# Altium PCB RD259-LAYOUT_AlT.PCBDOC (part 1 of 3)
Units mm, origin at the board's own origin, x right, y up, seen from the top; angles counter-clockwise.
Board outline 82.5 x 69.38 mm, 2 copper layers (TOP, BOTTOM), stack 0 mm thick; 80 components, 51 nets, 446 pads, 0 vias.
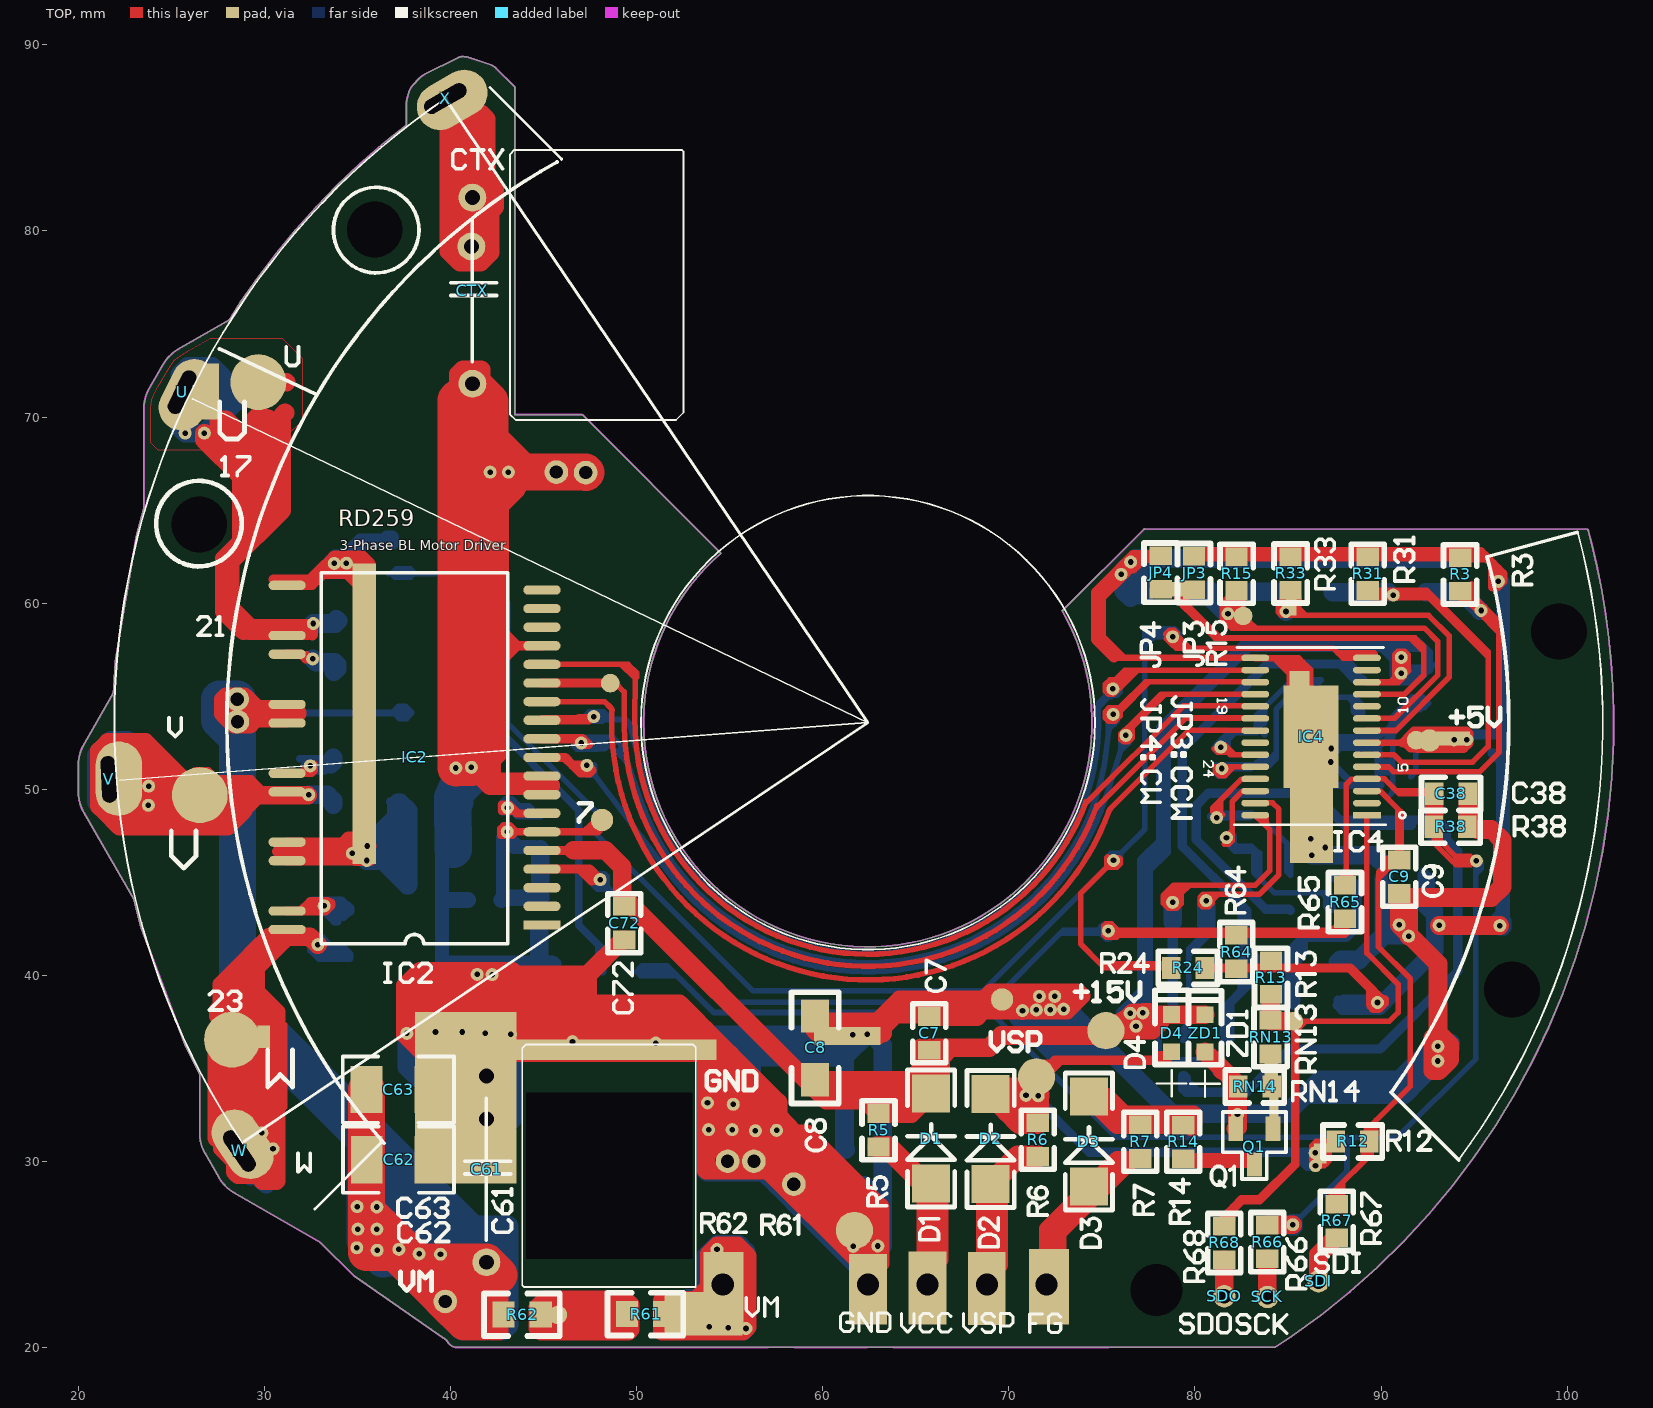
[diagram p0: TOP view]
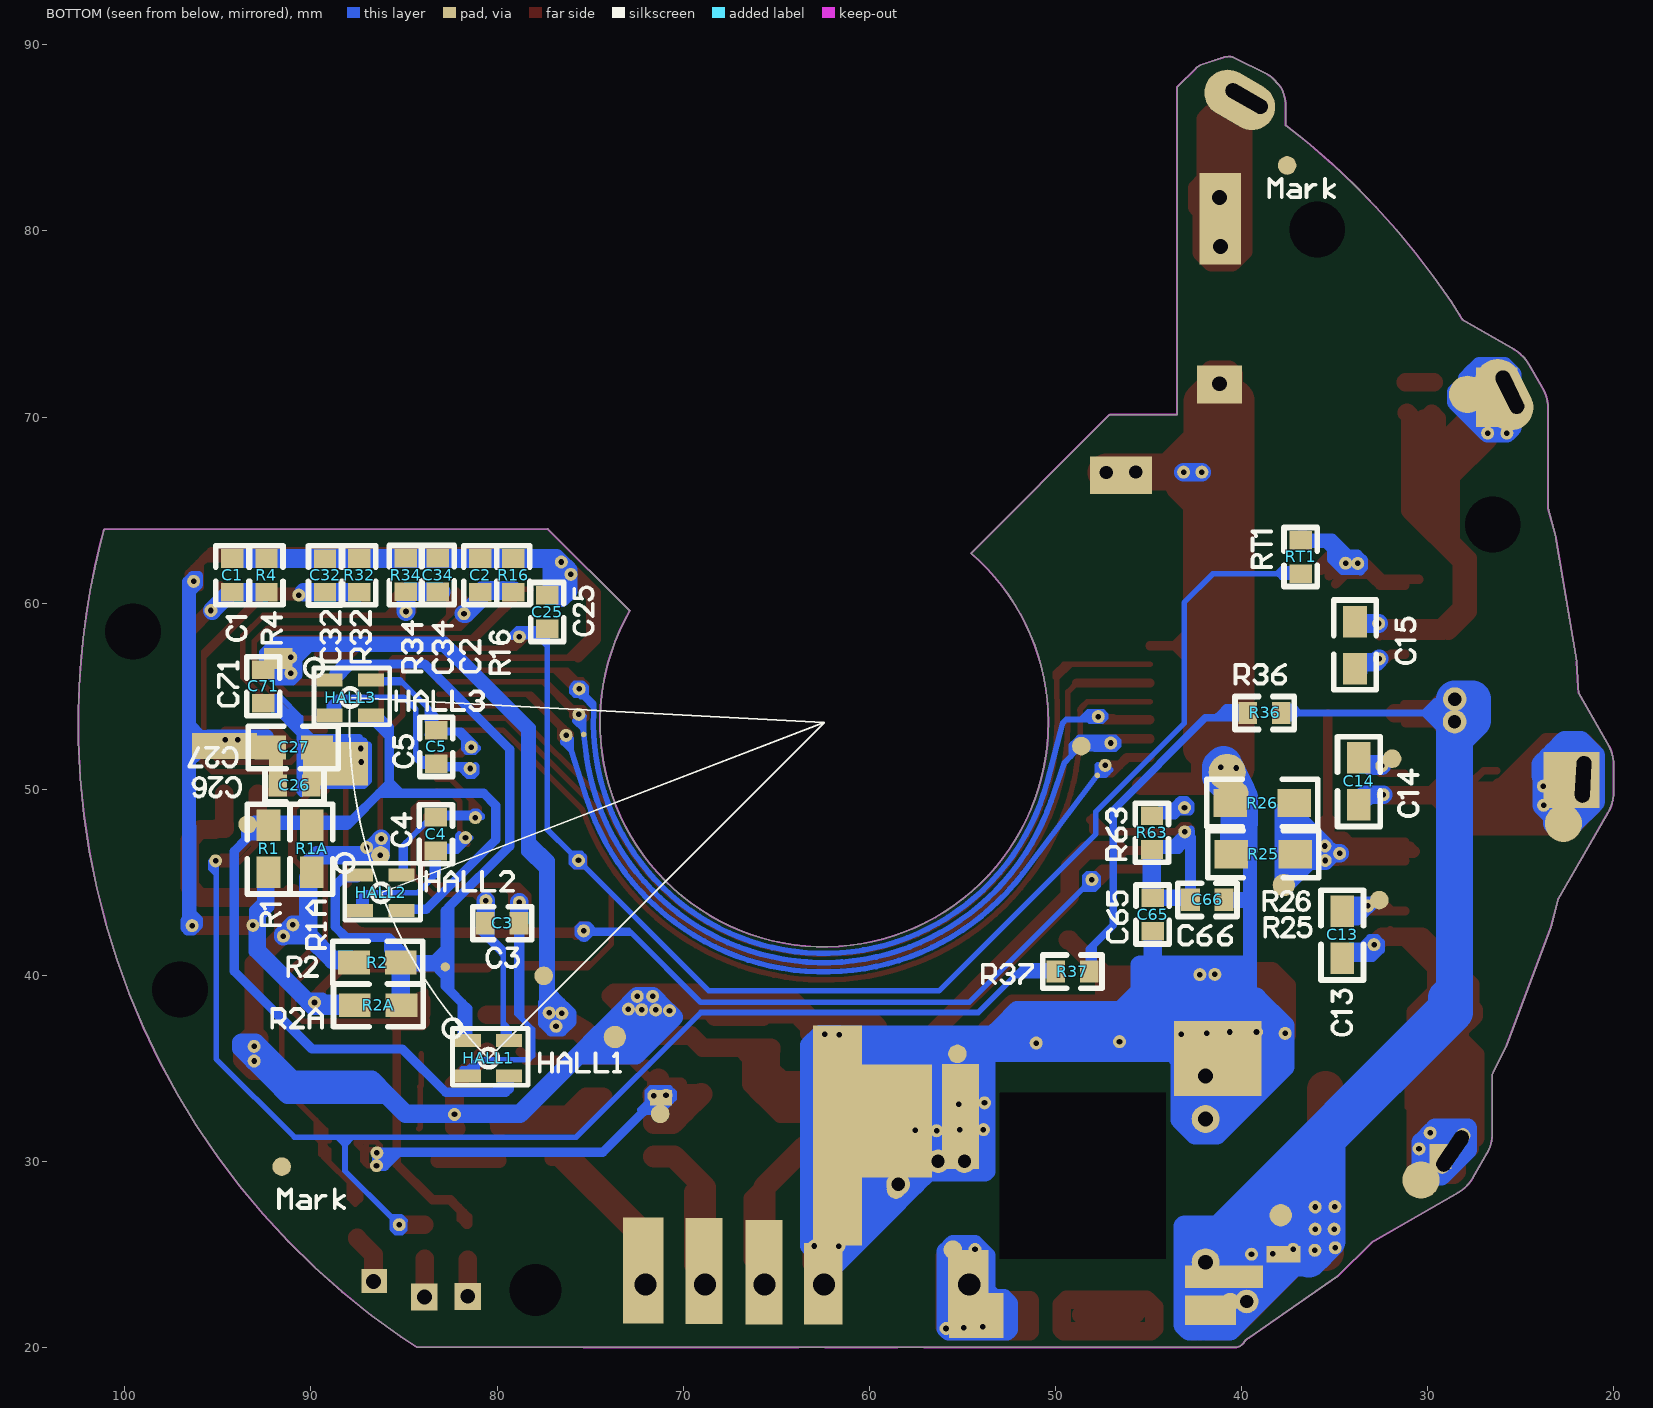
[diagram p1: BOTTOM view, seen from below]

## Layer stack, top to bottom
Top Solder: solder mask 0.0102, Solder Resist, Dk 3.5
TOP: signal copper (thickness not stored)
BOTTOM: signal copper (thickness not stored)
Bottom Solder: solder mask 0.0102, Solder Resist, Dk 3.5

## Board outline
40.344,20 40.34,20 40.337,20.001 40.333,20.001 40.331,20.002 40.259,20.003 40.121,20.042 39.996,20.113 39.893,20.213 39.854,20.277 39.851,20.282 39.849,20.288 39.847,20.293 39.846,20.296 39.823,20.329 39.77,20.39 39.709,20.443 39.642,20.489 39.607,20.508 39.603,20.509 39.595,20.511 39.588,20.514 39.581,20.518 34.873,23.794 34.871,23.795 34.868,23.797 34.865,23.799 34.862,23.802 34.86,23.803 34.847,23.812 34.841,23.818 34.835,23.824 34.83,23.831 34.828,23.834 33.004,25.636 28.356,28.32 28.233,28.391 28.008,28.564 27.807,28.764 27.634,28.989 27.562,29.111 27.561,29.113 27.56,29.116 26.808,30.417 26.807,30.419 26.806,30.422 26.805,30.425 26.804,30.426 26.734,30.549 26.627,30.81 26.555,31.083 26.518,31.362 26.518,31.504 26.518,31.506 26.518,34.672 26.466,34.783 25.765,36.193 25.762,36.196 25.757,36.202 25.753,36.209 25.749,36.216 23.385,42.538 23.384,42.54 23.381,42.546 23.379,42.551 23.377,42.556 23.374,42.568 23.361,42.604 23.359,42.61 23.358,42.617 23.357,42.624 23.357,42.627 22.974,44.093 20.292,48.739 20.221,48.862 20.112,49.125 20.038,49.401 20,49.683 20,49.827 20,49.83 20,49.832 20.001,49.835 20.001,49.836 20.001,51.469 20.038,51.752 20.112,52.027 20.221,52.291 21.877,55.159 21.9,55.476 21.984,56.839 21.983,56.843 21.981,56.853 21.98,56.862 21.98,56.871 23.099,63.5 23.098,63.505 23.096,63.516 23.095,63.527 23.097,63.538 23.102,63.559 23.102,63.562 23.102,63.569 23.102,63.576 23.104,63.583 23.518,65.088 23.518,70.454 23.518,70.596 23.556,70.879 23.629,71.155 23.739,71.418 24.56,72.841 24.63,72.963 24.802,73.186 25,73.386 25.223,73.559 25.345,73.63 25.346,73.631 25.349,73.633 25.351,73.635 25.354,73.637 28.114,75.229 28.139,75.267 28.14,75.269 28.142,75.275 28.144,75.281 28.147,75.286 28.275,75.479 28.275,75.483 28.277,75.493 28.28,75.502 28.284,75.51 28.726,76.198 29.66,77.53 30.646,78.824 31.683,80.077 32.77,81.287 33.904,82.453 35.084,83.572 36.308,84.644 36.83,85.065 37.621,85.677 37.621,86.837 cw(c38.621,86.837) 37.659,87.112 37.754,87.444 cw(c38.716,87.169) 37.987,87.854 38.319,88.207 cw(c39.047,87.522) 38.6,88.417 40.387,89.31 cw(c40.671,88.742) 40.671,89.377 cw(c40.671,88.453) 40.963,89.33 42.158,88.931 cw(c41.947,88.299) 42.437,88.752 43.44,87.748 43.444,87.745 43.45,87.736 43.453,87.727 43.455,87.717 43.455,84.083 43.456,84.081 43.456,84.079 43.456,84.077 43.456,70.128 47.068,70.128 47.078,70.126 47.088,70.122 47.096,70.116 47.099,70.113 54.528,62.683 54.529,62.683 ccw(c62.421,53.577) 72.865,59.587 72.866,59.587 77.265,63.977 77.273,63.983 77.282,63.986 77.292,63.988 101.089,63.963 101.104,63.959 101.117,63.95 101.126,63.938 101.129,63.93 101.131,63.927 101.136,63.92 101.139,63.913 101.142,63.906 101.311,63.271 101.606,62 101.86,60.719 102.072,59.431 102.241,58.137 102.369,56.837 102.454,55.535 102.496,54.23 102.496,52.583 102.397,50.597 102.2,48.618 101.906,46.651 101.513,44.701 101.025,42.774 100.442,40.872 99.765,39.002 98.996,37.168 98.137,35.375 97.191,33.626 96.159,31.926 95.043,30.279 93.848,28.69 92.575,27.162 91.228,25.699 89.81,24.305 88.324,22.983 86.775,21.736 85.166,20.567 84.329,20.02 84.318,20.015 84.307,20.012 84.295,20.011 84.289,20.011 75.37,20.011 75.365,20.009 75.356,20.005 75.347,20.002 75.337,20.001 63.816,20.001 63.806,20.003 63.797,20.005 63.788,20.009 63.783,20.011 62.396,20.011 62.391,20.009 62.382,20.005 62.373,20.002 62.363,20.001 58.508,20.001 58.498,20.002 58.488,20.005 58.479,20.009 58.475,20.011 57.07,20.011 57.065,20.009 57.056,20.005 57.047,20.002 57.037,20.001

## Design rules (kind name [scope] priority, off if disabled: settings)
AssemblyTestPointUsage [All] p0: scope1count=1 scope1_0_kind=Board scope1_0_value=Board scope2count=1 scope2_0_kind=Board scope2_0_value=Board commentlength=0
AssemblyTestpoint [All] p0: scope1count=1 scope1_0_kind=Board scope1_0_value=Board scope2count=1 scope2_0_kind=Board scope2_0_value=Board commentlength=0
Clearance [All] p0: scope1count=1 scope1_0_kind=Board scope1_0_value=Board scope2count=1 scope2_0_kind=Board scope2_0_value=Board commentlength=0 gap=0.15
Clearance [All] p1: gap=0.15 ignorepadtopadclearanceinfootprint=TRUE except(0.2: SMDPad-Fill SMDPad-Poly SMDPad-Region THPad-Fill THPad-Poly THPad-Region; 0.3: Arc-Hole Track-Hole SMDPad-Hole THPad-Hole Via-Hole Fill-Hole Poly-Hole Region-Hole Text-Hole)
ComponentClearance [All] p0: scope1count=1 scope1_0_kind=Board scope1_0_value=Board scope2count=1 scope2_0_kind=Board scope2_0_value=Board commentlength=0 gap=0.254 collisioncheckmode=3
DiffPairsRouting [All] p0: scope1count=1 scope1_0_kind=Board scope1_0_value=Board scope2count=1 scope2_0_kind=Board scope2_0_value=Board commentlength=0
FabricationTestPointUsage [All] p0: scope1count=1 scope1_0_kind=Board scope1_0_value=Board scope2count=1 scope2_0_kind=Board scope2_0_value=Board commentlength=0 valid=0 allowmultiple=FALSE
FabricationTestpoint [All] p0: scope1count=1 scope1_0_kind=Board scope1_0_value=Board scope2count=1 scope2_0_kind=Board scope2_0_value=Board commentlength=0 side=3 testpointundercomponent=TRUE minsize=1.016 maxsize=2.54 preferedsize=1.524 minholesize=0 maxholesize=1.016 preferedholesize=0.813 testpointgrid=0.025
FanoutControl Fanout_BGA [All] p0 off: scope1count=1 scope1_0_kind=Board scope1_0_value=Board scope2count=1 scope2_0_kind=Board scope2_0_value=Board commentlength=69 // Protel DXP Scope 1 Expression Was: IsBGA   Fanout_BGA (Default Rule)
FanoutControl Fanout_LCC [All] p0 off: scope1count=1 scope1_0_kind=Board scope1_0_value=Board scope2count=1 scope2_0_kind=Board scope2_0_value=Board commentlength=69 // Protel DXP Scope 1 Expression Was: IsLCC   Fanout_LCC (Default Rule)
FanoutControl Fanout_SOIC [All] p0 off: scope1count=1 scope1_0_kind=Board scope1_0_value=Board scope2count=1 scope2_0_kind=Board scope2_0_value=Board commentlength=71 // Protel DXP Scope 1 Expression Was: IsSOIC   Fanout_SOIC (Default Rule)
FanoutControl Fanout_Small [All] p0 off: scope1count=1 scope1_0_kind=Board scope1_0_value=Board scope2count=1 scope2_0_kind=Board scope2_0_value=Board commentlength=84 // Protel DXP Scope 1 Expression Was: (CompPinCount < 5)   Fanout_Small (Default Rule)
FanoutControl Fanout_Default [All] p0: scope1count=1 scope1_0_kind=Board scope1_0_value=Board scope2count=1 scope2_0_kind=Board scope2_0_value=Board commentlength=30 // Fanout_Default (Default Rule)
Height [All] p0: scope1count=1 scope1_0_kind=Board scope1_0_value=Board scope2count=1 scope2_0_kind=Board scope2_0_value=Board commentlength=0
HoleSize [All] p0: scope1count=1 scope1_0_kind=Board scope1_0_value=Board scope2count=1 scope2_0_kind=Board scope2_0_value=Board commentlength=0 absolutevalues=TRUE maxlimit=100 minlimit=0.001 maxpercent=80.000 minpercent=20.000
HoleSize [All] p1: absolutevalues=TRUE maxlimit=100 minlimit=0.001 maxpercent=80.000 minpercent=20.000
HoleToHoleClearance [All] p0: scope1count=1 scope1_0_kind=Board scope1_0_value=Board scope2count=1 scope2_0_kind=Board scope2_0_value=Board commentlength=0
HoleToHoleClearance [All] p1: gap=0.4 allowstackedmicrovias=FALSE
LayerPairs [All] p0: scope1count=1 scope1_0_kind=Board scope1_0_value=Board scope2count=1 scope2_0_kind=Board scope2_0_value=Board commentlength=0 enforce=TRUE
MinimumSolderMaskSliver [All] p0: scope1count=1 scope1_0_kind=Board scope1_0_value=Board scope2count=1 scope2_0_kind=Board scope2_0_value=Board commentlength=0
MinimumSolderMaskSliver [All] p1: minsoldermaskwidth=0.1
NetAntennae [All] p0: scope1count=1 scope1_0_kind=Board scope1_0_value=Board scope2count=1 scope2_0_kind=Board scope2_0_value=Board commentlength=0
NetAntennae [All] p1: netantennaetolerance=100
PasteMaskExpansion [All] p0: scope1count=1 scope1_0_kind=Board scope1_0_value=Board scope2count=1 scope2_0_kind=Board scope2_0_value=Board commentlength=0 expansion=0
PlaneClearance [All] p0: scope1count=1 scope1_0_kind=Board scope1_0_value=Board scope2count=1 scope2_0_kind=Board scope2_0_value=Board commentlength=0 clearance=0.001
PlaneClearance [All] p1: clearance=0.001
PlaneConnect [All] p0: scope1count=1 scope1_0_kind=Board scope1_0_value=Board scope2count=1 scope2_0_kind=Board scope2_0_value=Board commentlength=0 planeconnectstyle=Direct reliefexpansion=0.508 reliefentries=4 reliefconductorwidth=0.254 reliefairgap=0.254
PlaneConnect [All] p1: planeconnectstyle=Direct reliefexpansion=0.508 reliefentries=4 reliefconductorwidth=0.254 reliefairgap=0.254
PolygonConnect [All] p0: scope1count=1 scope1_0_kind=Board scope1_0_value=Board scope2count=1 scope2_0_kind=Board scope2_0_value=Board commentlength=0 connectstyle=Direct reliefconductorwidth=0.254 reliefentries=4 polygonreliefangle="90 Angle"
PolygonConnect [All] p1: connectstyle=Direct reliefconductorwidth=0.254 reliefentries=4 polygonreliefangle="90 Angle" airgapwidth=0.254
RoutingCorners [All] p0: scope1count=1 scope1_0_kind=Board scope1_0_value=Board scope2count=1 scope2_0_kind=Board scope2_0_value=Board commentlength=0 cornerstyle=45-Degree minsetback=2.54 maxsetback=2.54
RoutingLayers [All] p0: scope1count=1 scope1_0_kind=Board scope1_0_value=Board scope2count=1 scope2_0_kind=Board scope2_0_value=Board commentlength=0 top layer=Automatic bottom layer=Automatic
RoutingPriority [All] p0: scope1count=1 scope1_0_kind=Board scope1_0_value=Board scope2count=1 scope2_0_kind=Board scope2_0_value=Board commentlength=0
RoutingTopology [All] p0: scope1count=1 scope1_0_kind=Board scope1_0_value=Board scope2count=1 scope2_0_kind=Board scope2_0_value=Board commentlength=0 topology=Shortest
RoutingVias [All] p0: scope1count=1 scope1_0_kind=Board scope1_0_value=Board scope2count=1 scope2_0_kind=Board scope2_0_value=Board commentlength=0 holewidth=0.1 width=0.1 viastyle="Through Hole" minholewidth=0.001 minwidth=0.001 maxholewidth=100 maxwidth=100
RoutingVias [All] p1: holewidth=0.1 width=0.1 viastyle="Through Hole" minholewidth=0.001 minwidth=0.001 maxholewidth=100 maxwidth=100
ShortCircuit [All] p0: scope1count=1 scope1_0_kind=Board scope1_0_value=Board scope2count=1 scope2_0_kind=Board scope2_0_value=Board commentlength=0 allowed=FALSE
SilkToBoardRegionClearance [All] p0: scope1count=1 scope1_0_kind=Board scope1_0_value=Board scope2count=1 scope2_0_kind=Board scope2_0_value=Board commentlength=0
SilkToSilkClearance [All] p0: scope1count=1 scope1_0_kind=Board scope1_0_value=Board scope2count=1 scope2_0_kind=Board scope2_0_value=Board commentlength=0
SilkToSilkClearance [All] p1: silktosilkclearance=0.001
SilkToSolderMaskClearance [All] p0 off: scope1count=1 scope1_0_kind=Board scope1_0_value=Board scope2count=1 scope2_0_kind=Board scope2_0_value=Board commentlength=44 // Protel DXP Scope 1 Expression Was: IsPad
SilkToSolderMaskClearance [IsPad] p1: minsilkscreentomaskgap=0 clearancetoexposedcopper=TRUE
SolderMaskExpansion [All] p0: scope1count=1 scope1_0_kind=Board scope1_0_value=Board scope2count=1 scope2_0_kind=Board scope2_0_value=Board commentlength=0 expansion=0.001
SolderMaskExpansion [All] p1: expansion=0.001
UnRoutedNet [All] p0: scope1count=1 scope1_0_kind=Board scope1_0_value=Board scope2count=1 scope2_0_kind=Board scope2_0_value=Board commentlength=0
UnpouredPolygon [All] p0: scope1count=1 scope1_0_kind=Board scope1_0_value=Board scope2count=1 scope2_0_kind=Board scope2_0_value=Board commentlength=0
Width [All] p0: scope1count=1 scope1_0_kind=Board scope1_0_value=Board scope2count=1 scope2_0_kind=Board scope2_0_value=Board commentlength=0 maxlimit=1000 minlimit=2539.975 preferedwidth=0
Width [All] p1: maxlimit=1000 minlimit=2539.975 preferedwidth=0 toplayer_minwidth=0 bottomlayer_minwidth=0 minimp=50.000000 maximp=50.000000 favimp=50.000000
22 further rules are at their usual default settings.

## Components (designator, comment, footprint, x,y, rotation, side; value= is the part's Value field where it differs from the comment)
C1 "0603-1" 0603-1#1 94.227,62.397 r90 bottom
C2 "0603-1" 0603-1#1 80.898,62.397 r90 bottom
C3 "0603-1" 0603-1#1 80.627,42.79 r0 bottom
C4 "0603-1" 0603-1#1 83.288,48.483 r90 bottom
C5 "0603-1" 0603-1#1 83.27,53.175 r90 bottom
C7 "0603-1" 0603-1#2 65.722,35.979 r90 top
C8 "1206-1" 1206-1#1 59.833,34.39 r90 top
C9 "0603-1" 0603-1#2 90.976,46.196 r270 top
C13 "0805-1" 0805-1 34.578,40.918 r270 bottom
C14 "0805-1" 0805-1 33.684,49.171 r270 bottom
C25 "0603-1" 0603-1#1 77.304,60.424 r90 bottom
C26 "0603-1" 0603-1#1 91.791,50.201 r0 bottom
C27 "0805-1" 0805-1 92.194,52.242 r0 bottom
C32 "0603-1" 0603-1#1 89.247,62.392 r90 bottom
C34 "0603-1" 0603-1#1 83.189,62.41 r90 bottom
C38 "0603-1" 0603-1#2 94.661,49.748 r180 top
C61 "C-CBB" C-CBB 41.921,24.577 r90 top
C62 "1210" 1210 35.487,30.089 r0 top
C63 "1210" 1210 35.477,33.858 r0 top
C65 "0603-1" 0603-1#1 44.77,44.165 r90 bottom
C66 "0603-1" 0603-1#1 42.736,44.052 r0 bottom
C71 "0603-1" 0603-1#1 92.567,56.428 r90 bottom
C72 "0603-1" 0603-1#2 49.333,43.7 r270 top
CTX "C-CBB" C-CBB 41.169,71.79 r90 top
D1 "RS1M-SMD" RS1M-SMD 65.813,28.801 r90 top
D2 "RS1M-SMD" RS1M-SMD 69.011,28.777 r90 top
D3 "RS1M-SMD" RS1M-SMD 74.297,28.64 r90 top
D4 "D0603" D0603 78.747,35.886 r90 top
HALL1 "HW101-A" HW101-A 80.187,35.688 r0 bottom
HALL2 "HW101-A" HW101-A 85.973,44.573 r0 bottom
HALL3 "HW101-A" HW101-A 87.625,55.064 r0 bottom
IC2 "SSOP30-TPD4204F" SSOP30-TPD4204F 44.911,42.706 r180 top
IC4 "TC78B043FNG" TC78B043FNG 89.242,48.602 r180 top
JP3 "0603-1" 0603-1#2 79.951,62.519 r270 top
JP4 "0603-1" 0603-1#2 78.156,62.544 r270 top
Q1 "SOT23-NPN" SOT23-NPN 83.084,29.785 r180 top
R1 "0805-1" 0805-1 92.283,45.538 r270 bottom
R1A "0805-1" 0805-1 89.963,45.538 r270 bottom
R2 "0805-1" 0805-1 85.171,40.685 r180 bottom
R2A "0805-1" 0805-1 85.139,38.381 r180 bottom
R3 "0603-1" 0603-1#2 94.252,62.446 r270 top
R4 "0603-1" 0603-1#1 92.395,62.397 r90 bottom
R5 "0603-1" 0603-1#2 62.996,30.769 r90 top
R6 "0603-1" 0603-1#2 71.549,30.26 r90 top
R7 "0603-1" 0603-1#2 77.062,30.154 r90 top
R12 "0603-1" 0603-1#2 87.572,31.066 r0 top
R13 "0603-1" 0603-1#2 84.087,40.774 r270 top
R14 "0603-1" 0603-1#2 79.372,31.948 r270 top
R15 "0603-1" 0603-1#2 82.238,60.679 r90 top
R16 "0603-1" 0603-1#1 79.125,62.397 r90 bottom
R24 "0603-1" 0603-1#2 78.72,40.394 r0 top
R25 "1206-1" 1206-1#2 40.535,46.257 r0 bottom
R26 "1206-1" 1206-1#2 40.585,49.009 r0 bottom
R31 "0603-1" 0603-1#2 89.284,62.483 r270 top
R32 "0603-1" 0603-1#1 87.415,62.397 r90 bottom
R33 "0603-1" 0603-1#2 85.14,60.691 r90 top
R34 "0603-1" 0603-1#1 84.907,62.409 r90 bottom
R36 "0603-1" 0603-1#1 37.852,54.095 r180 bottom
R37 "0603-1" 0603-1#1 48.177,40.199 r180 bottom
R38 "0603-1" 0603-1#2 94.641,47.983 r180 top
R61 "0805-2" 0805-2 51.481,21.79 r180 top
R62 "0805-2" 0805-2 44.844,21.757 r180 top
R63 "0603-1" 0603-1#1 44.806,48.563 r90 bottom
R64 "0603-1" 0603-1#2 82.219,40.343 r90 top
R65 "0603-1" 0603-1#2 88.066,44.833 r270 top
R66 "0603-1" 0603-1#2 83.889,26.563 r270 top
R67 "0603-1" 0603-1#2 87.615,27.698 r270 top
R68 "0603-1" 0603-1#2 81.57,26.514 r270 top
RN13 "0603-1" 0603-1#2 84.064,37.574 r270 top
RN14 "0603-1" 0603-1#2 84.122,34.02 r180 top
RT1 "0603-1" 0603-1#1 36.816,61.578 r270 bottom
SCK "PAD_FOR_BLDC_S50_1_2_3" PAD_FOR_BLDC_S50_1_2_3 83.898,22.711 r0 top
SDI "PAD_FOR_BLDC_S50_1_2_3" PAD_FOR_BLDC_S50_1_2_3 86.641,23.552 r0 top
SDO "PAD_FOR_BLDC_S50_1_2_3" PAD_FOR_BLDC_S50_1_2_3 81.576,22.747 r0 top
U "PAD_FOR_BLDC_S50_1_2_U" PAD_FOR_BLDC_S50_1_2_U 25.819,71.544 r154 top
V "PAD_FOR_BLDC_S50_V" PAD_FOR_BLDC_S50_V 21.548,51.1 r183 top
W "PAD_FOR_BLDC_S50_1_W" PAD_FOR_BLDC_S50_1_W 28.245,30.509 r214 top
X "PAD_FOR_BLDC_S50_1_2_3_4_X" PAD_FOR_BLDC_S50_1_2_3_4_X 39.718,87.112 r120 top
ZD1 "D0603" D0603 80.543,35.874 r90 top
? "0805-1" 0805-1 33.894,58.993 r90 bottom

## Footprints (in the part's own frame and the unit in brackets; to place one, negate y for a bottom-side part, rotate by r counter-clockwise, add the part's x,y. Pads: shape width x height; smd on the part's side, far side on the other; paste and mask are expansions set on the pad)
0603-1#1 [mm] "KC00080BKP"
  rect 1x1.2 smd paste-1.403 mask+0: 1(0,0) 2(-1.803,0)
0603-1#2 [mm] "KC00080BKP"
  rect 1x1.2 smd paste-1.403 mask+0: 1(0,0) 2(1.803,0)
0805-1 [mm] "KC00080BKP"
  rect 1.7x1.27 smd paste-1.903 mask+0: 1(0,0) 2(-2.515,0)
0805-2 [mm] "KC00080BKP"
  rect 1.2x1.4 smd paste-1.603 mask+0: 1(0,0) 2(2,0)
1206-1#1 [mm] "KC00080BKP"
  rect 1.8x1.524 smd paste-2.003 mask+0: 1(-0.008,0.248) 2(3.421,0.248)
1206-1#2 [mm] "KC00080BKP"
  rect 1.8x1.524 smd paste-2.003 mask+0: 1(0.008,-0.248) 2(-3.421,-0.248)
1210 [mm] "KC00080BKP"
  rect 1.7x2.54 smd paste-2.743 mask+0: 1(0,0) 2(3.429,0)
C-CBB [mm] "KC00080BKP"
  round 1.5 / inner round 0 / far side round 1.5 hole 0.8 paste-1.703 mask+0: 1(0,0) 2(10,0)
D0603 [mm] "KC00080BKP"
  rect 0.9x0.9 smd paste-1.103 mask+0: 1(0,0) 2(2,0)
HW101-A [mm] "KC00080BKP"
  rect 1.4x0.7 smd paste-1.603 mask+0: 1(1.387,-0.809) 2(1.387,1.091) 3(-0.838,1.091) 4(-0.838,-0.809)
PAD_FOR_BLDC_S50_1_2_3 [mm] "KC00080BKP"
  round 1.2 / inner round 0 / far side round 1.2 hole 0.8 paste-1.403 mask+0: 1(0,0)
PAD_FOR_BLDC_S50_1_2_3_4_X [mm] "KC00080BKP"
  round 0.8 / inner round 0 / far side round 0.8 hole 0.8 slot 2.5 at 90 deg paste-2.5 mask+0: 1(0,0)
PAD_FOR_BLDC_S50_1_2_U [mm] "KC00080BKP"
  round 0.8 / inner round 0 / far side round 0.8 hole 0.8 slot 2.5 at 90 deg paste-2.5 mask+0: 1(0.133,0.295)
PAD_FOR_BLDC_S50_1_W [mm] "KC00080BKP"
  oval 0.8x2.8 / inner round 0 / far side oval 0.8x2.8 hole 0.8 slot 2.5 at 90 deg paste-2.5 mask+0: 1(-0.363,0.187)
PAD_FOR_BLDC_S50_V [mm] "KC00080BKP"
  round 0.8 / inner round 0 / far side round 0.8 hole 0.8 slot 2.5 at 90 deg paste-2.5 mask+0: 1(-0.053,0.577)
RS1M-SMD [mil] "KC00080BKP"
  rect 80x80 smd paste-88 mask+0: 1(0.49,-0.36) 2(190.49,-0.36)
SOT23-NPN [mm] "KC00080BKP"
  rect 0.8x1.3 smd paste-1.503 mask+0: 1(-1.112,-1.964) 2(-0.123,-0.05) 3(0.888,-1.964)
SSOP30-TPD4204F [mm] "KC00080BKP"
  rect 2x0.5 smd paste-2.203 mask+0: 1(0,0)
  oval 2x0.5 smd paste-2.203 mask+0: 2(0,-1) 3(0,-2) 4(0,-3) 5(0,-4) 6(0,-5) 7(0,-6) 8(0,-7) 9(0,-8) 10(0,-9) 11(0,-10) 12(0,-11) 13(0,-12) 14(0,-13) 15(0,-14) 16(0,-15) 17(0,-16) 18(0,-17) 19(0,-18) 20(13.7,-18.25) 21(13.7,-15.55) 22(13.7,-14.55) 23(13.7,-11.85) 24(13.7,-10.85) 25(13.7,-8.15) 26(13.7,-7.15) 27(13.7,-4.45) 28(13.7,-3.45) 29(13.7,-0.75) 30(13.7,0.25)
TC78B043FNG [mm] "KC00080BKP"
  rect 2.95x5.5 smd paste-5.703 mask+0: 0(3,-4.225)
  rect 1.5x0.35 smd paste-1.703 mask+0: 1(0,0)
  oval 1.5x0.35 smd paste-1.703 mask+0: 2(0,-0.65) 3(0,-1.3) 4(0,-1.95) 5(0,-2.6) 6(0,-3.25) 7(0,-3.9) 8(0,-4.55) 9(0,-5.2) 10(0,-5.85) 11(0,-6.5) 12(0,-7.15) 13(0,-7.8) 14(0,-8.45) 15(6,-8.45) 16(6,-7.8) 17(6,-7.15) 18(6,-6.5) 19(6,-5.85) 20(6,-5.2) 21(6,-4.55) 22(6,-3.9) 23(6,-3.25) 24(6,-2.6) 25(6,-1.95) 26(6,-1.3) 27(6,-0.65) 28(6,0)

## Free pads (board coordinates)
  oval 2.5x4 smd paste-4.203 mask+0: ""(22.173,50.564)
  rect 3x3 smd far side paste-3 mask+0: ""(22.259,50.494)
  round 2 smd far side paste-2 mask+0: ""(22.693,48.165) ""(27.848,71.222) ""(30.348,28.998) ""(40.76,50.903)
  round 0.7 / inner round 0 / far side round 0.7 hole 0.3 paste-0.903 mask+0: ""(23.755,49.135) ""(23.77,50.165) ""(25.733,69.135) ""(26.765,69.135) ""(29.853,31.532) ""(30.452,30.671) ""(32.376,49.702) ""(32.454,51.253) ""(32.586,57.006) ""(32.623,58.906) ""(32.869,41.643) ""(33.203,43.73) ""(33.746,62.133) ""(34.399,62.144) ""(34.721,46.547) ""(34.957,25.355) ""(34.976,27.566) ""(35.015,26.355) ""(35.493,46.167) ""(35.511,46.947) ""(36.034,26.355) ""(36.034,27.547) ""(36.053,25.22) ""(37.22,25.268) ""(37.649,36.874) ""(38.303,25.028) ""(39.188,36.951) ""(39.457,25.008) ""(40.283,51.138) ""(40.63,36.951) ""(41.117,51.174) ""(41.426,40.045) ""(41.861,36.874) ""(42.123,67.039) ""(42.233,40.033) ""(43.043,47.709) ""(43.055,49.011) ""(43.107,67.039) ""(43.221,36.827) ""(46.551,36.43) ""(47.018,52.48) ""(47.323,51.283) ""(47.692,53.902) ""(48.038,45.136) ""(51.026,36.357) ""(53.804,33.143) ""(53.861,31.701) ""(53.908,21.109) ""(54.315,25.264) ""(54.93,21.055) ""(55.131,31.701) ""(55.188,33.066) ""(55.874,21.017) ""(56.381,31.643) ""(57.515,31.662) ""(61.601,36.796) ""(61.631,25.431) ""(62.383,36.821) ""(62.958,25.451) ""(70.733,38.103) ""(70.92,33.547) ""(71.476,38.136) ""(71.579,33.525) ""(71.639,38.867) ""(72.23,38.147) ""(72.467,38.867) ""(72.94,38.181) ""(75.349,42.385) ""(75.593,55.388) ""(75.605,54.02) ""(75.626,46.17) ""(76.035,61.546) ""(76.289,52.896) ""(76.518,37.959) ""(76.545,62.21) ""(76.833,37.26) ""(77.199,37.981) ""(78.799,43.921) ""(78.806,58.19) ""(80.601,44.008) ""(81.166,48.471) ""(81.388,52.259) ""(81.45,51.112) ""(81.697,47.398) ""(81.776,59.429) ""(82.289,32.52) ""(84.893,59.551) ""(85.259,26.594) ""(86.219,47.345) ""(86.268,46.441) ""(86.456,30.455) ""(86.48,29.77) ""(87.013,46.868) ""(87.302,51.46) ""(87.322,52.184) ""(89.81,38.538) ""(90.66,60.433) ""(90.972,42.707) ""(91.082,56.231) ""(91.088,57.081) ""(91.485,42.1) ""(93.057,35.391) ""(93.06,36.176) ""(93.122,42.683) ""(93.926,52.653) ""(94.613,52.665) ""(95.129,46.15) ""(95.376,59.604) ""(96.308,61.17) ""(96.39,42.665)
  oval 2.5x4 smd rot 154 paste-2.7 mask+0: ""(25.89,71.194)
  oval 2.5x4 smd far side rot 154 paste-2.7 mask+0: ""(25.89,71.194)
  rect 2.212x3.21 smd far side paste-3.21 mask+0: ""(26.274,71.063)
  round 0 hole 3 unplated paste-3 mask+0: ""(26.491,64.217) ""(35.921,80.077) ""(97.041,39.237) ""(99.561,58.467)
  round 3 smd paste-3 mask+0: ""(26.522,49.681) ""(28.253,36.543) ""(29.666,71.876)
  rect 0.991x3.023 smd paste-3.023 mask+0: ""(27.051,71.37)
  round 1.27 / inner round 0 / far side round 1.27 hole 0.711 paste-1.473 mask+0: ""(28.53,54.838) ""(28.542,53.629) ""(39.715,22.469) ""(45.682,67.039) ""(47.257,67.014) ""(54.886,30.006) ""(56.299,30.006) ""(58.445,28.774)
  oval 2.5x4 smd rot 34 paste-2.7 mask+0: ""(28.824,30.917)
  rect 1.164x1.331 smd far side paste-1.331 mask+0: ""(29.3,30.267)
  rect 0.662x1.193 smd paste-1.193 mask+0: ""(29.961,36.701)
  round 1 smd far side paste-1 mask+0: ""(31.898,51.639) ""(32.589,44.038) ""(37.542,83.52) ""(40.593,22.436) ""(48.602,52.317) ""(55.261,35.775) ""(55.506,25.249) ""(58.56,28.481) ""(65.764,26.235) ""(68.773,26.324) ""(71.235,32.547) ""(72.117,26.304) ""(77.304,60.424) ""(77.492,39.969) ""(80.998,60.593) ""(86.268,46.441) ""(91.575,29.715) ""(93.405,48.107)
  rect 1.263x16.155 smd paste-16.155 mask+0: ""(35.352,54.055)
  round 1.2 smd far side paste-1.2 mask+0: ""(37.719,44.848) ""(37.88,27.105) ""(40.216,49.798) ""(61.496,26.989) ""(73.67,36.682)
  rect 1.828x0.868 smd far side paste-1.828 mask+0: ""(37.725,25.007)
  oval 2.5x4 smd rot 120 paste-2.7 mask+0: ""(40.084,87.046)
  oval 2.5x4 smd far side rot 120 paste-2.7 mask+0: ""(40.084,87.046)
  rect 5.462x9.231 smd paste-9.231 mask+0: ""(40.822,33.413)
  rect 4.19x1.211 smd far side paste-4.19 mask+0: ""(40.944,23.807)
  round 1.5 / inner round 0 / far side round 1.5 hole 0.8 paste-1.703 mask+0: ""(41.114,79.17) ""(41.921,32.277)
  rect 2.231x4.915 smd far side paste-4.915 mask+0: ""(41.13,80.653)
  rect 2.404x2.058 smd far side paste-2.404 mask+0: ""(41.178,71.75)
  rect 4.699x4.053 smd far side paste-4.699 mask+0: ""(41.261,35.528)
  rect 2.749x1.57 smd far side paste-2.749 mask+0: ""(41.665,21.999)
  round 1 smd paste-1 mask+0: ""(45.764,21.749) ""(48.577,55.698) ""(65.722,35.979) ""(82.592,59.314) ""(85.321,37.532) ""(90.976,44.393) ""(91.887,52.632)
  rect 3.353x2.007 smd far side paste-3.353 mask+0: ""(46.469,66.874)
  round 0.3 smd far side paste-0.3 mask+0: ""(47.735,50.742) ""(75.35,52.941) ""(80.998,60.593)
  round 1.2 smd paste-1.2 mask+0: ""(48.139,48.346) ""(69.635,38.699) ""(92.606,52.617)
  round 0 hole 8.907 square unplated paste-11.7 mask+0: ""(48.519,29.227)
  rect 11.352x1.099 smd paste-11.352 mask+0: ""(48.612,36.006)
  rect 4.211x2.314 smd paste-4.211 mask+0: ""(53.587,21.808)
  rect 2.949x2.411 smd far side paste-2.949 mask+0: ""(54.246,21.712)
  oval 1.8x2.5 / inner round 0 / far side oval 1.8x2.5 hole 1.2 paste-2.703 mask+0: ""(54.628,23.378) ""(62.428,23.378) ""(65.628,23.378) ""(68.828,23.378) ""(72.028,23.378)
  rect 2.132x3.829 smd paste-3.829 mask+0: ""(54.662,23.21)
  rect 2.174x3.97 smd far side paste-3.97 mask+0: ""(54.669,23.252)
  rect 1.981x5.635 smd far side paste-5.635 mask+0: ""(55.102,32.403)
  rect 4.303x6.088 smd far side paste-6.088 mask+0: ""(58.778,32.166)
  rect 3.575x0.965 smd paste-3.575 mask+0: ""(61.32,36.748)
  rect 2.64x11.821 smd far side paste-11.821 mask+0: ""(61.7,31.399)
  round 2 smd paste-2 mask+0: ""(61.702,26.285) ""(71.491,34.541) ""(75.217,37.022)
  rect 2.032x3.81 smd paste-3.81 mask+0: ""(62.437,23.124)
  rect 2.053x4.36 smd far side paste-4.36 mask+0: ""(62.473,23.419)
  rect 2.032x3.937 smd paste-3.937 mask+0: ""(65.626,23.189) ""(68.814,23.17)
  rect 1.995x5.596 smd far side paste-5.596 mask+0: ""(65.658,24.037)
  rect 2.009x5.697 smd far side paste-5.697 mask+0: ""(68.88,24.101)
  rect 1.173x0.827 smd far side paste-1.173 mask+0: ""(71.198,33.417)
  rect 2.181x5.683 smd far side paste-5.683 mask+0: ""(72.144,24.137)
  rect 2.161x4.064 smd paste-4.064 mask+0: ""(72.157,23.25)
  round 0 hole 2.8 unplated paste-2.8 mask+0: ""(77.927,23.076)
  rect 1.23x0.775 smd paste-1.23 mask+0: ""(79.059,60.74)
  rect 1.427x1.445 smd far side paste-1.445 mask+0: ""(81.576,22.744)
  round 0.5 smd far side paste-0.5 mask+0: ""(82.784,40.451)
  rect 1.403x1.451 smd far side paste-1.451 mask+0: ""(83.916,22.699)
  rect 0.736x1.73 smd paste-1.73 mask+0: ""(84.108,35.099)
  rect 0.5x1.721 smd paste-1.721 mask+0: ""(84.247,32.965)
  rect 0.576x1.099 smd paste-1.099 mask+0: ""(85.181,59.894)
  rect 1.1x0.878 smd paste-1.1 mask+0: ""(85.62,55.925)
  rect 2.322x4.924 smd paste-4.924 mask+0: ""(86.268,48.487)
  rect 1.364x1.285 smd far side paste-1.364 mask+0: ""(86.606,23.574)
  rect 0.688x1.055 smd paste-1.055 mask+0: ""(86.74,30.424)
  rect 3.487x2.33 smd far side paste-3.487 mask+0: ""(88.677,51.366)
  rect 1.543x1.135 smd far side paste-1.543 mask+0: ""(91.765,57.026)
  rect 0.734x1.954 smd far side paste-1.954 mask+0: ""(91.879,51.141)
  rect 2.441x0.757 smd paste-2.441 mask+0: ""(93.556,52.731)
  rect 3.492x1.379 smd far side paste-3.492 mask+0: ""(94.65,52.322)

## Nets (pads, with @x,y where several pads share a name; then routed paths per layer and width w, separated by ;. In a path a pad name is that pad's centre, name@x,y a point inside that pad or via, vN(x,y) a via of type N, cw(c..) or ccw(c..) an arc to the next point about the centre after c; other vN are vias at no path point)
+7V: C65.1 C66.1 IC2.6 pad.@43.043,47.709 pad.@48.139,48.346 R63.2 | length 25.4
  TOP w0.4: pad.@43.043,47.709 43.046,47.706 43.5,47.706 ; pad.@47.986,48.487 pad.@47.596,48.096 ; pad.@48.139,48.346 47.986,48.193 47.986,47.788 47.905,47.706 ; 43.5,47.706 43.179,48.027 42.848,48.027 42.705,47.884 42.705,47.521 43.314,47.521 43.5,47.706 ; 43.5,47.706 IC2.6@44.911,47.706 47.206,47.706 ; 47.206,47.706 47.905,47.706 ; 47.206,47.706 pad.@47.596,48.096 ; pad.@47.596,48.096 47.596,48.015 47.702,47.909 47.905,47.706
  BOTTOM w0.4: 42.72,47.857 42.72,47.772 42.683,47.735 42.683,47.404 42.736,47.351 43.101,46.987 ; pad.@42.962,47.709 pad.@43.043,47.709 pad.@43.101,47.652 ; 43.101,46.987 43.194,46.893 ; 43.101,46.987 pad.@43.101,47.652 ; pad.@43.101,47.652 43.397,47.355 ; 43.194,46.893 43.86,46.893 ; 43.194,46.893 43.361,46.726 44.026,46.726 ; 43.194,46.893 43.194,47.153 43.397,47.355 ; 43.397,47.355 43.693,47.059 ; 43.693,47.059 44.506,47.059 R63.2@44.806,46.759 44.773,46.726 44.026,46.726 ; 43.693,47.059 43.86,46.893 ; 43.86,46.893 44.026,46.726
  BOTTOM w0.6: C66.1@42.736,44.052 42.736,47.351 42.736,47.402 pad.@43.043,47.709
  BOTTOM w0.864: C66.1@42.736,44.052 42.848,44.165 C65.1@44.77,44.165
  BOTTOM w1: C65.1@44.806,44.165 R63.2@44.806,46.759
BSU: ?.2 IC2.22 pad.@32.586,57.006 | length 4.8
  TOP w0.4: IC2.22@31.233,57.302 31.279,57.256 31.298,57.237 31.98,57.237 32.274,57.237 pad.@32.505,57.006
  TOP w0.5: IC2.22@31.211,57.256 31.279,57.256 31.961,57.256 31.98,57.237 32.212,57.006 32.505,57.006 pad.@32.586,57.006
  BOTTOM w1: pad.@32.586,57.006 32.764,56.828 33.759,56.828 33.894,56.693 ?.2@33.894,56.478 ?.2@33.728,56.312
BSV: C14.2 IC2.25 pad.@31.898,51.639 pad.@32.454,51.253 | length 5.9
  TOP w0.4: IC2.25@31.211,50.856 IC2.25@31.988,50.856 ; pad.@32.454,51.253 32.385,51.253 IC2.25@31.988,50.856 ; pad.@32.684,51.346 32.684,50.991 32.55,50.856 IC2.25@31.988,50.856
  BOTTOM w0.4: pad.@31.898,51.639 33.637,51.639 C14.2@33.684,51.686
  BOTTOM w1: pad.@32.454,51.253 33.098,51.253 33.181,51.336 33.549,51.336 33.684,51.471 C14.2@33.684,51.686
BSW: C13.2 IC2.29 pad.@32.589,44.038 pad.@33.203,43.73 | length 13.2
  TOP w0.5: IC2.29@31.211,43.456 IC2.29@31.961,43.456 ; 33.574,43.874 33.574,43.768 ; IC2.29@31.961,43.456 32.856,43.456 ; IC2.29@31.961,43.456 32.449,43.944 pad.@32.934,43.944 ; 32.856,43.456 33.261,43.456 33.369,43.564 33.574,43.768 ; 32.856,43.456 33.092,43.692 33.165,43.692 pad.@33.203,43.73 33.149,43.73 pad.@32.934,43.944 ; pad.@32.934,43.944 33.397,43.944 33.574,43.768
  BOTTOM w0.4: 33.927,42.871 33.757,42.871 33.524,43.103 ; C13.2@34.443,43.73 34.443,43.738 34.143,44.038 pad.@32.589,44.038 33.05,43.577 33.255,43.372 ; C13.2@34.578,43.433 C13.2@34.517,43.372 ; 33.255,43.372 C13.2@34.517,43.372 ; 33.255,43.372 33.524,43.103 ; 33.524,43.103 34.248,43.103 C13.2@34.517,43.372
  BOTTOM w0.5: pad.@33.203,43.73 34.443,43.73 34.578,43.595 C13.2@34.578,43.433 C13.2@34.58,43.436
DIAG: IC2.4 pad.@48.038,45.136 pad.@75.349,42.385 R64.2 R65.2 | length 76.4
  TOP w0.3: pad.@75.349,42.385 75.367,42.404 75.868,42.404 ; pad.@75.572,42.148 75.895,42.148 ; R65.2@88.066,43.03 87.966,43.03 R65.2@87.697,42.761 ; 75.868,42.404 75.617,42.654 75.518,42.754 75.212,42.754 75.11,42.651 75.11,42.173 75.123,42.159 75.224,42.058 75.804,42.058 75.895,42.148 ; 75.868,42.404 77.405,42.404 ; 75.895,42.148 77.661,42.148 ; 77.405,42.404 87.182,42.404 ; 77.405,42.404 77.661,42.148 ; 77.661,42.148 87.445,42.148 ; 87.182,42.404 87.223,42.444 87.38,42.444 R65.2@87.616,42.68 ; 87.182,42.404 87.616,42.404 ; 87.445,42.148 87.616,42.319 87.616,42.404 ; 87.445,42.148 87.75,42.148 ; 87.616,42.404 R65.2@87.616,42.68 ; 87.616,42.404 87.664,42.404 87.75,42.319 ; R65.2@87.616,42.68 R65.2@87.697,42.761 ; R65.2@87.697,42.761 R65.2@87.831,42.761 ; 87.75,42.148 87.75,42.319 ; 87.75,42.148 87.902,42.148 ; 87.75,42.319 87.75,42.68 R65.2@87.831,42.761 ; R65.2@87.831,42.761 R65.2@87.923,42.761 ; 87.902,42.148 87.902,42.74 R65.2@87.923,42.761 ; 87.902,42.148 88.054,42.148 88.149,42.243 88.149,42.761 R65.2@87.923,42.761
  TOP w0.5: IC2.4@44.911,45.706 46.942,45.706 ; 46.942,45.706 47.568,45.081 47.585,45.098 47.999,45.098 pad.@48.038,45.136 47.468,45.706 46.942,45.706
  BOTTOM w0.3: pad.@48.038,45.136 48.291,44.882 ; 75.021,42.143 pad.@75.215,42.143 ; 75.276,41.949 75.337,41.949 75.355,41.967 ; pad.@75.349,42.385 75.321,42.413 74.762,42.413 ; 47.7,44.984 47.793,44.891 47.801,44.882 48.291,44.882 ; 47.7,44.984 47.7,45.163 47.688,45.175 47.688,45.271 47.795,45.378 47.864,45.447 48.287,45.447 48.318,45.416 48.418,45.315 48.418,44.756 ; 47.7,44.984 47.7,44.804 47.876,44.629 48.545,44.629 ; 48.291,44.882 48.418,44.756 ; 48.418,44.756 48.545,44.629 ; 48.545,44.629 54.635,38.539 69.056,38.539 72.777,42.26 ; 72.777,42.26 72.93,42.413 74.762,42.413 ; 72.777,42.26 74.904,42.26 75.197,41.967 75.355,41.967 ; 74.762,42.413 75.041,42.692 75.088,42.739 75.495,42.739 75.598,42.635 75.689,42.544 75.689,42.198 75.612,42.121 75.458,41.967 75.355,41.967
DIR: IC4.11 JP3.2 JP4.2 pad.@79.059,60.74 | length 28
  TOP w0.3: JP4.2@78.156,60.741 pad.@79.041,60.741 ; pad.@79.249,60.484 pad.@79.202,60.436 ; IC4.11@89.242,55.102 91.269,55.102 92.298,56.131 92.298,57.396 ; pad.@79.041,60.741 79.927,60.741 JP3.2@79.951,60.716 79.899,60.716 79.549,60.366 79.549,59.955 ; pad.@79.041,60.741 79.004,60.704 79.004,60.409 79.017,60.396 79.017,60.184 79.202,59.999 ; 79.202,59.999 pad.@79.202,60.436 ; 79.202,59.999 79.398,59.803 ; pad.@79.202,60.436 79.398,60.241 79.398,60.022 ; 79.398,59.803 79.398,60.022 ; 79.398,59.803 79.549,59.652 ; 79.398,60.022 79.483,60.022 79.549,59.955 ; 79.549,59.652 79.549,59.955 ; 79.549,59.652 81.076,58.125 81.379,58.125 ; 79.549,59.955 81.379,58.125 ; 81.379,58.125 91.569,58.125 ; 91.569,58.125 91.83,58.125 92.298,57.657 92.298,57.396 ; 91.569,58.125 92.298,57.396
FG: D3.1 pad.@72.028,23.378 pad.@72.117,26.304 pad.@72.144,24.137 pad.@72.157,23.25 R7.1 | length 16.6
  TOP w0.8: pad.@72.028,23.378 72.028,26.374 D3.1@74.306,28.653 75.808,30.154 R7.1@76.739,30.154 ; pad.@72.593,24.835 72.689,24.931 72.689,26.105 R7.1@76.739,30.154 ; R7.1@77.062,30.154 R7.1@76.739,30.154
FGC: C1.2 IC4.5 pad.@95.376,59.604 R3.2 R4.2 | length 26.8
  TOP w0.3: IC4.5@89.242,51.202 89.252,51.192 90.425,51.192 90.671,50.947 95.31,50.947 96.343,51.979 96.343,58.403 ; R3.2@94.252,60.642 94.326,60.569 94.326,60.116 94.63,60.116 95.259,59.487 96.343,58.403 ; R3.2@94.352,60.642 95.376,59.618 pad.@95.376,59.604 96.343,58.638 ; 94.862,61.033 94.91,60.985 94.91,60.936 94.953,60.894 94.953,60.408 95.566,59.794 96.343,59.018 96.343,58.638 ; 96.343,58.403 96.343,58.638
  BOTTOM w0.3: pad.@95.316,59.604 pad.@95.376,59.604
  BOTTOM w1: R4.2@92.395,60.593 C1.2@94.227,60.593 94.327,60.593 pad.@95.316,59.604
FGOUT: IC4.1 pad.@85.321,37.532 R13.2 R68.1 RN13.1 | length 49.9
  TOP w0.3: RN13.1@83.817,37.821 RN13.1@83.873,37.765 ; R13.2@83.839,38.648 R13.2@83.839,39.127 ; RN13.1@84.064,37.896 RN13.1@84.064,37.574 ; RN13.1@84.064,37.956 RN13.1@83.873,37.765 ; RN13.1@84.106,37.532 RN13.1@84.064,37.574 ; pad.@85.278,37.532 85.321,37.574 85.363,37.532 85.944,37.532 ; IC4.1@89.242,48.602 89.242,41.19 90.916,39.516 90.916,38 90.447,37.532 85.944,37.532 ; R68.1@81.57,26.514 81.479,26.604 81.479,27.034 81.749,27.304 ; R68.1@81.57,26.514 81.67,26.514 82.02,26.864 82.02,27.286 ; R68.1@81.57,26.514 81.749,26.693 81.749,27.304 ; 81.749,27.304 82.02,27.574 ; 82.02,27.286 82.02,27.574 ; 82.02,27.286 82.556,27.822 ; 82.02,27.574 82.489,28.043 82.777,28.043 ; 82.556,27.822 82.777,28.043 ; 82.556,27.822 83.488,27.822 83.709,28.043 ; 82.777,28.043 83.454,28.043 ; 83.454,28.043 83.709,28.043 ; 83.454,28.043 85.321,29.91 ; 83.709,28.043 85.321,29.655 ; RN13.1@83.873,37.765 RN13.1@84.064,37.574 ; 85.321,29.655 85.321,29.91 ; 85.321,29.655 85.466,29.8 85.466,37.042 ; 85.321,29.91 85.321,36.896 ; 85.321,36.896 pad.@85.321,37.532 85.455,37.398 85.455,37.053 85.466,37.042 ; 85.321,36.896 85.466,37.042 ; 85.466,37.042 85.944,37.519 85.944,37.532
  TOP w1: RN13.1@84.064,37.956 R13.2@84.064,38.621 ; RN13.1@84.106,37.532 pad.@85.278,37.532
